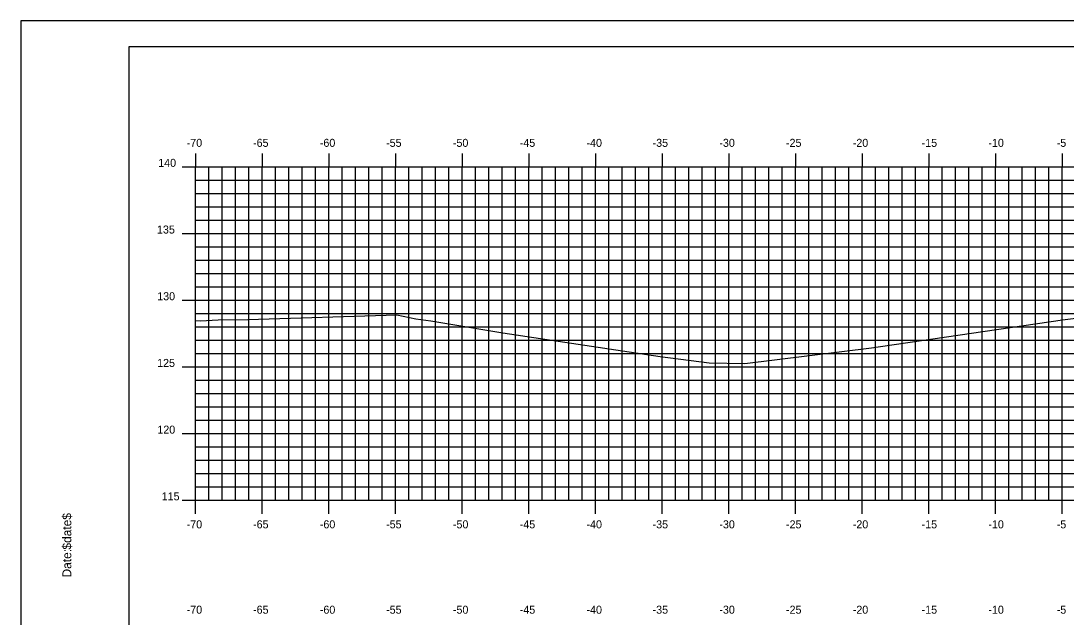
# Model space of a CAD drawing. Extents: x 851073 to 851245, y 365624 to 365734.
# Drawn here: x 851073.2 to 851151.5, y 365689.3 to 365734 of the extents above; entities that cross this region are included whole.
import ezdxf

# ---------------------------------------------------------------- set-up
doc = ezdxf.new("R2010")
doc.units = 0
for name, color, linetype in [('BORDER', 7, 'Continuous'), ('H_V ANNOTATION', 7, 'Continuous'), ('MAJOR', 7, 'Continuous'), ('MINOR', 7, 'Continuous'), ('PLOT BOUNDARY', 7, 'Continuous'), ('S_Roadway_Centerline', 7, 'Continuous')]:
    doc.layers.add(name, color=color, linetype=linetype)

msp = doc.modelspace()

# ---------------------------------------------------------------- linework, layer by layer
at = {"layer": 'BORDER'}
msp.add_lwpolyline([(851081.253, 365627.027), (851241.253, 365627.027), (851241.253, 365732.027), (851081.253, 365732.027)], close=True, dxfattribs=at)
at = {"layer": 'MAJOR'}
for p, q in [((851086.253, 365724.029), (851086.253, 365723.027)), ((851091.253, 365724.029), (851091.253, 365723.027)), ((851096.253, 365724.029), (851096.253, 365723.027)), ((851101.253, 365724.029), (851101.253, 365723.027)), ((851106.253, 365724.029), (851106.253, 365723.027)), ((851111.253, 365724.029), (851111.253, 365723.027)), ((851116.253, 365724.029), (851116.253, 365723.027)), ((851121.253, 365724.029), (851121.253, 365723.027)), ((851126.253, 365724.029), (851126.253, 365723.027)), ((851131.253, 365724.029), (851131.253, 365723.027)), ((851136.253, 365724.029), (851136.253, 365723.027)), ((851141.253, 365724.029), (851141.253, 365723.027)), ((851146.253, 365724.029), (851146.253, 365723.027)), ((851151.253, 365724.029), (851151.253, 365723.027)), ((851085.251, 365723.027), (851086.253, 365723.027)), ((851086.253, 365723.027), (851226.253, 365723.027)), ((851086.253, 365698.027), (851086.253, 365723.027)), ((851086.253, 365698.027), (851086.253, 365723.027)), ((851086.253, 365723.027), (851226.253, 365723.027)), ((851091.253, 365698.027), (851091.253, 365723.027)), ((851096.253, 365698.027), (851096.253, 365723.027)), ((851101.253, 365698.027), (851101.253, 365723.027)), ((851106.253, 365698.027), (851106.253, 365723.027)), ((851111.253, 365698.027), (851111.253, 365723.027)), ((851116.253, 365698.027), (851116.253, 365723.027)), ((851121.253, 365698.027), (851121.253, 365723.027)), ((851126.253, 365698.027), (851126.253, 365723.027)), ((851131.253, 365698.027), (851131.253, 365723.027)), ((851136.253, 365698.027), (851136.253, 365723.027)), ((851141.253, 365698.027), (851141.253, 365723.027)), ((851146.253, 365698.027), (851146.253, 365723.027)), ((851151.253, 365698.027), (851151.253, 365723.027)), ((851085.251, 365718.027), (851086.253, 365718.027)), ((851086.253, 365718.027), (851226.253, 365718.027)), ((851085.251, 365713.027), (851086.253, 365713.027)), ((851086.253, 365713.027), (851226.253, 365713.027)), ((851085.251, 365708.027), (851086.253, 365708.027)), ((851086.253, 365708.027), (851226.253, 365708.027)), ((851085.251, 365703.027), (851086.253, 365703.027)), ((851086.253, 365703.027), (851226.253, 365703.027)), ((851085.251, 365698.027), (851086.253, 365698.027)), ((851086.253, 365698.027), (851226.253, 365698.027)), ((851086.253, 365698.027), (851226.253, 365698.027)), ((851086.253, 365697.025), (851086.253, 365698.027)), ((851091.253, 365697.025), (851091.253, 365698.027)), ((851096.253, 365697.025), (851096.253, 365698.027)), ((851101.253, 365697.025), (851101.253, 365698.027)), ((851106.253, 365697.025), (851106.253, 365698.027)), ((851111.253, 365697.025), (851111.253, 365698.027)), ((851116.253, 365697.025), (851116.253, 365698.027)), ((851121.253, 365697.025), (851121.253, 365698.027)), ((851126.253, 365697.025), (851126.253, 365698.027)), ((851131.253, 365697.025), (851131.253, 365698.027)), ((851136.253, 365697.025), (851136.253, 365698.027)), ((851141.253, 365697.025), (851141.253, 365698.027)), ((851146.253, 365697.025), (851146.253, 365698.027)), ((851151.253, 365697.025), (851151.253, 365698.027))]:
    msp.add_line(p, q, dxfattribs=at)
at = {"layer": 'MINOR'}
for p, q in [((851087.253, 365698.027), (851087.253, 365723.027)), ((851088.253, 365698.027), (851088.253, 365723.027)), ((851089.253, 365698.027), (851089.253, 365723.027)), ((851090.253, 365698.027), (851090.253, 365723.027)), ((851092.253, 365698.027), (851092.253, 365723.027)), ((851093.253, 365698.027), (851093.253, 365723.027)), ((851094.253, 365698.027), (851094.253, 365723.027)), ((851095.253, 365698.027), (851095.253, 365723.027)), ((851097.253, 365698.027), (851097.253, 365723.027)), ((851098.253, 365698.027), (851098.253, 365723.027)), ((851099.253, 365698.027), (851099.253, 365723.027)), ((851100.253, 365698.027), (851100.253, 365723.027)), ((851102.253, 365698.027), (851102.253, 365723.027)), ((851103.253, 365698.027), (851103.253, 365723.027)), ((851104.253, 365698.027), (851104.253, 365723.027)), ((851105.253, 365698.027), (851105.253, 365723.027)), ((851107.253, 365698.027), (851107.253, 365723.027)), ((851108.253, 365698.027), (851108.253, 365723.027)), ((851109.253, 365698.027), (851109.253, 365723.027)), ((851110.253, 365698.027), (851110.253, 365723.027)), ((851112.253, 365698.027), (851112.253, 365723.027)), ((851113.253, 365698.027), (851113.253, 365723.027)), ((851114.253, 365698.027), (851114.253, 365723.027)), ((851115.253, 365698.027), (851115.253, 365723.027)), ((851117.253, 365698.027), (851117.253, 365723.027)), ((851118.253, 365698.027), (851118.253, 365723.027)), ((851119.253, 365698.027), (851119.253, 365723.027)), ((851120.253, 365698.027), (851120.253, 365723.027)), ((851122.253, 365698.027), (851122.253, 365723.027)), ((851123.253, 365698.027), (851123.253, 365723.027)), ((851124.253, 365698.027), (851124.253, 365723.027)), ((851125.253, 365698.027), (851125.253, 365723.027)), ((851127.253, 365698.027), (851127.253, 365723.027)), ((851128.253, 365698.027), (851128.253, 365723.027)), ((851129.253, 365698.027), (851129.253, 365723.027)), ((851130.253, 365698.027), (851130.253, 365723.027)), ((851132.253, 365698.027), (851132.253, 365723.027)), ((851133.253, 365698.027), (851133.253, 365723.027)), ((851134.253, 365698.027), (851134.253, 365723.027)), ((851135.253, 365698.027), (851135.253, 365723.027)), ((851137.253, 365698.027), (851137.253, 365723.027)), ((851138.253, 365698.027), (851138.253, 365723.027)), ((851139.253, 365698.027), (851139.253, 365723.027)), ((851140.253, 365698.027), (851140.253, 365723.027)), ((851142.253, 365698.027), (851142.253, 365723.027)), ((851143.253, 365698.027), (851143.253, 365723.027)), ((851144.253, 365698.027), (851144.253, 365723.027)), ((851145.253, 365698.027), (851145.253, 365723.027)), ((851147.253, 365698.027), (851147.253, 365723.027)), ((851148.253, 365698.027), (851148.253, 365723.027)), ((851149.253, 365698.027), (851149.253, 365723.027)), ((851150.253, 365698.027), (851150.253, 365723.027)), ((851086.253, 365722.027), (851226.253, 365722.027)), ((851086.253, 365722.027), (851087.255, 365722.027)), ((851086.253, 365721.027), (851226.253, 365721.027)), ((851086.253, 365721.027), (851087.255, 365721.027)), ((851086.253, 365720.027), (851226.253, 365720.027)), ((851086.253, 365720.027), (851087.255, 365720.027)), ((851086.253, 365719.027), (851226.253, 365719.027)), ((851086.253, 365719.027), (851087.255, 365719.027)), ((851086.253, 365717.027), (851226.253, 365717.027)), ((851086.253, 365717.027), (851087.255, 365717.027)), ((851086.253, 365716.027), (851226.253, 365716.027)), ((851086.253, 365716.027), (851087.255, 365716.027)), ((851086.253, 365715.027), (851226.253, 365715.027)), ((851086.253, 365715.027), (851087.255, 365715.027)), ((851086.253, 365714.027), (851226.253, 365714.027)), ((851086.253, 365714.027), (851087.255, 365714.027)), ((851086.253, 365712.027), (851226.253, 365712.027)), ((851086.253, 365712.027), (851087.255, 365712.027)), ((851086.253, 365711.027), (851226.253, 365711.027)), ((851086.253, 365711.027), (851087.255, 365711.027)), ((851086.253, 365710.027), (851226.253, 365710.027)), ((851086.253, 365710.027), (851087.255, 365710.027)), ((851086.253, 365709.027), (851226.253, 365709.027)), ((851086.253, 365709.027), (851087.255, 365709.027)), ((851086.253, 365707.027), (851226.253, 365707.027)), ((851086.253, 365707.027), (851087.255, 365707.027)), ((851086.253, 365706.027), (851226.253, 365706.027)), ((851086.253, 365706.027), (851087.255, 365706.027)), ((851086.253, 365705.027), (851226.253, 365705.027)), ((851086.253, 365705.027), (851087.255, 365705.027)), ((851086.253, 365704.027), (851226.253, 365704.027)), ((851086.253, 365704.027), (851087.255, 365704.027)), ((851086.253, 365702.027), (851226.253, 365702.027)), ((851086.253, 365702.027), (851087.255, 365702.027)), ((851086.253, 365701.027), (851226.253, 365701.027)), ((851086.253, 365701.027), (851087.255, 365701.027)), ((851086.253, 365700.027), (851226.253, 365700.027)), ((851086.253, 365700.027), (851087.255, 365700.027)), ((851086.253, 365699.027), (851226.253, 365699.027)), ((851086.253, 365699.027), (851087.255, 365699.027))]:
    msp.add_line(p, q, dxfattribs=at)
at = {"layer": 'PLOT BOUNDARY'}
msp.add_lwpolyline([(851073.159, 365623.968), (851243.159, 365623.968), (851243.159, 365733.968), (851073.159, 365733.968)], close=True, dxfattribs=at)
at = {"layer": 'S_Roadway_Centerline'}
msp.add_lwpolyline([(851086.253, 365711.509), (851086.636, 365711.481), (851087.944, 365711.548), (851090.183, 365711.591), (851101.364, 365711.936), (851102.771, 365711.621), (851103.894, 365711.482), (851109.294, 365710.593), (851121.097, 365708.807), (851124.785, 365708.345), (851127.453, 365708.274), (851136.94, 365709.454), (851137.628, 365709.559), (851151.273, 365711.565), (851153.26, 365711.799)], dxfattribs=at)

# ---------------------------------------------------------------- texts
at = {"layer": 'BORDER'}
for s, p in [('$date$', (851076.938, 365694.332)), ('Date:', (851076.938, 365692.244))]:
    msp.add_text(s, height=0.6696, rotation=90, dxfattribs=at).set_placement(p)
at = {"layer": 'H_V ANNOTATION'}
for s, p in [('-70', (851085.594, 365724.527)), ('-65', (851090.57, 365724.527)), ('-60', (851095.578, 365724.527)), ('-55', (851100.549, 365724.527)), ('-50', (851105.557, 365724.527)), ('-45', (851110.57, 365724.527)), ('-40', (851115.578, 365724.527)), ('-35', (851120.533, 365724.527)), ('-30', (851125.541, 365724.527)), ('-25', (851130.538, 365724.527)), ('-20', (851135.546, 365724.527)), ('-15', (851140.709, 365724.527)), ('-10', (851145.717, 365724.527)), ('-5', (851150.843, 365724.527)), ('140', (851083.457, 365723.027)), ('135', (851083.366, 365718.027)), ('130', (851083.382, 365713.027)), ('125', (851083.377, 365708.027)), ('120', (851083.393, 365703.027)), ('115', (851083.72, 365698.027)), ('-70', (851085.594, 365695.927)), ('-65', (851090.57, 365695.927)), ('-60', (851095.578, 365695.927)), ('-55', (851100.549, 365695.927)), ('-50', (851105.557, 365695.927)), ('-45', (851110.57, 365695.927)), ('-40', (851115.578, 365695.927)), ('-35', (851120.533, 365695.927)), ('-30', (851125.541, 365695.927)), ('-25', (851130.538, 365695.927)), ('-20', (851135.546, 365695.927)), ('-15', (851140.709, 365695.927)), ('-10', (851145.717, 365695.927)), ('-5', (851150.843, 365695.927)), ('-70', (851085.594, 365689.527)), ('-65', (851090.57, 365689.527)), ('-60', (851095.578, 365689.527)), ('-55', (851100.549, 365689.527)), ('-50', (851105.557, 365689.527)), ('-45', (851110.57, 365689.527)), ('-40', (851115.578, 365689.527)), ('-35', (851120.533, 365689.527)), ('-30', (851125.541, 365689.527)), ('-25', (851130.538, 365689.527)), ('-20', (851135.546, 365689.527)), ('-15', (851140.709, 365689.527)), ('-10', (851145.717, 365689.527)), ('-5', (851150.843, 365689.527))]:
    msp.add_text(s, height=0.6, dxfattribs=at).set_placement(p)
at = {"layer": 'MAJOR'}
msp.add_text('-', height=0.006, dxfattribs=at).set_placement((851086.248, 365698.027))

doc.saveas('drawing.dxf')
